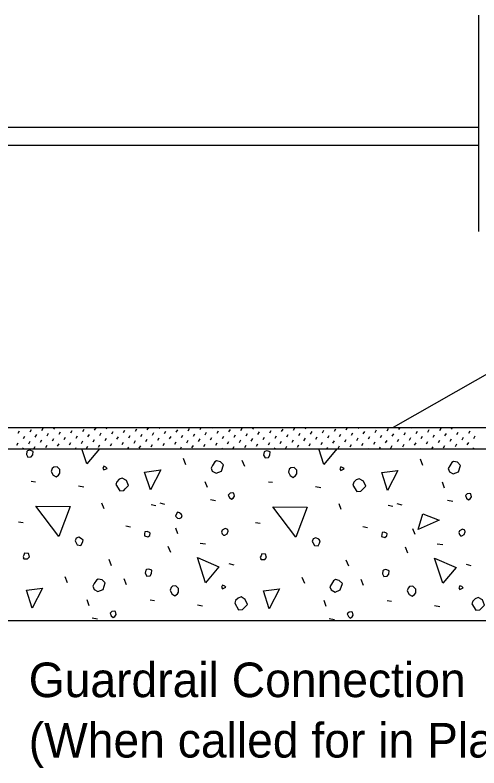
# Model space of a CAD drawing. Extents: x 0 to 41.1, y 0 to 25.9.
# Drawn here: x 34.613 to 37.318, y 9.7 to 14.089 of the extents above; entities that cross this region are included whole.
import ezdxf

# ---------------------------------------------------------------- set-up
doc = ezdxf.new("R2010")
doc.units = 0
for name, color, linetype in [('Dimension', 7, 'Continuous'), ('Miscellaneous', 7, 'Continuous'), ('TrafBarrierConc', 7, 'Continuous')]:
    doc.layers.add(name, color=color, linetype=linetype)

msp = doc.modelspace()

# ---------------------------------------------------------------- linework, layer by layer
at = {"layer": 'Miscellaneous'}
for p, q in [((37.3177, 12.8265), (37.3177, 14.0888)), ((34.77, 11.6673), (34.7781, 11.6813)), ((34.8391, 11.6754), (34.8446, 11.6848)), ((34.9083, 11.6835), (34.909, 11.6848)), ((35.008, 11.6611), (35.0161, 11.6751)), ((35.0772, 11.6692), (35.0853, 11.6832)), ((35.1463, 11.6773), (35.1507, 11.6848)), ((35.3152, 11.663), (35.3233, 11.677)), ((35.3844, 11.6711), (35.3923, 11.6848)), ((35.4535, 11.6792), (35.4568, 11.6848)), ((35.6224, 11.6649), (35.6305, 11.6789)), ((35.6915, 11.673), (35.6984, 11.6848)), ((35.7607, 11.6811), (35.7629, 11.6848)), ((35.9296, 11.6667), (35.9377, 11.6807)), ((35.9987, 11.6748), (36.0045, 11.6848)), ((36.0679, 11.6829), (36.069, 11.6848)), ((36.2368, 11.6686), (36.2449, 11.6826)), ((36.3059, 11.6767), (36.3106, 11.6848)), ((36.4748, 11.6624), (36.4829, 11.6764)), ((36.5439, 11.6705), (36.552, 11.6845)), ((36.6131, 11.6786), (36.6167, 11.6848)), ((36.782, 11.6643), (36.7901, 11.6783)), ((36.8511, 11.6724), (36.8583, 11.6848)), ((36.9203, 11.6805), (36.9228, 11.6848)), ((37.0891, 11.6661), (37.0972, 11.6801)), ((37.1583, 11.6742), (37.1644, 11.6848)), ((37.2275, 11.6823), (37.2289, 11.6848)), ((34.6317, 11.6511), (34.6398, 11.6651)), ((34.6622, 11.6206), (34.6703, 11.6346)), ((34.7008, 11.6592), (34.7089, 11.6732)), ((34.7314, 11.6287), (34.7395, 11.6427)), ((34.8005, 11.6368), (34.8086, 11.6508)), ((34.8697, 11.6449), (34.8778, 11.6589)), ((34.9388, 11.653), (34.9469, 11.667)), ((34.9694, 11.6225), (34.9775, 11.6365)), ((35.0385, 11.6306), (35.0466, 11.6446)), ((35.1077, 11.6387), (35.1158, 11.6527)), ((35.1769, 11.6468), (35.185, 11.6608)), ((35.246, 11.6549), (35.2541, 11.6689)), ((35.2766, 11.6243), (35.2847, 11.6383)), ((35.3457, 11.6324), (35.3538, 11.6464)), ((35.4149, 11.6405), (35.423, 11.6545)), ((35.4841, 11.6487), (35.4922, 11.6626)), ((35.5146, 11.6181), (35.5227, 11.6321)), ((35.5532, 11.6568), (35.5613, 11.6707)), ((35.5837, 11.6262), (35.5918, 11.6402)), ((35.6529, 11.6343), (35.661, 11.6483)), ((35.7221, 11.6424), (35.7302, 11.6564)), ((35.7912, 11.6505), (35.7993, 11.6645)), ((35.8218, 11.62), (35.8299, 11.634)), ((35.8604, 11.6586), (35.8685, 11.6726)), ((35.8909, 11.6281), (35.899, 11.6421)), ((35.9601, 11.6362), (35.9682, 11.6502)), ((36.0293, 11.6443), (36.0374, 11.6583)), ((36.0984, 11.6524), (36.1065, 11.6664)), ((36.129, 11.6219), (36.1371, 11.6359)), ((36.1676, 11.6605), (36.1757, 11.6745)), ((36.1981, 11.63), (36.2062, 11.644)), ((36.2673, 11.6381), (36.2754, 11.6521)), ((36.3364, 11.6462), (36.3445, 11.6602)), ((36.4056, 11.6543), (36.4137, 11.6683)), ((36.4361, 11.6238), (36.4442, 11.6378)), ((36.5053, 11.6319), (36.5134, 11.6459)), ((36.5745, 11.64), (36.5826, 11.654)), ((36.6436, 11.6481), (36.6517, 11.6621)), ((36.6742, 11.6175), (36.6823, 11.6315)), ((36.7128, 11.6562), (36.7209, 11.6702)), ((36.7433, 11.6256), (36.7514, 11.6396)), ((36.8125, 11.6337), (36.8206, 11.6477)), ((36.8817, 11.6418), (36.8898, 11.6558)), ((36.9508, 11.6499), (36.9589, 11.6639)), ((36.9814, 11.6194), (36.9895, 11.6334)), ((37.02, 11.658), (37.0281, 11.672)), ((37.0505, 11.6275), (37.0586, 11.6415)), ((37.1197, 11.6356), (37.1278, 11.6496)), ((37.1888, 11.6437), (37.1969, 11.6577)), ((37.258, 11.6518), (37.2661, 11.6658)), ((37.2885, 11.6213), (37.2966, 11.6353)), ((34.6236, 11.582), (34.6317, 11.596)), ((34.6927, 11.5901), (34.7008, 11.6041)), ((34.7619, 11.5982), (34.77, 11.6122)), ((34.831, 11.6063), (34.8391, 11.6203)), ((34.8616, 11.5757), (34.8697, 11.5897)), ((34.9002, 11.6144), (34.9083, 11.6284)), ((34.9307, 11.5838), (34.9388, 11.5978)), ((34.9999, 11.5919), (35.008, 11.6059)), ((35.0691, 11.6), (35.0772, 11.614)), ((35.1382, 11.6081), (35.1463, 11.6221)), ((35.1688, 11.5776), (35.1769, 11.5916)), ((35.2074, 11.6162), (35.2155, 11.6302)), ((35.2379, 11.5857), (35.246, 11.5997)), ((35.3071, 11.5938), (35.3152, 11.6078)), ((35.3763, 11.6019), (35.3844, 11.6159)), ((35.4454, 11.61), (35.4535, 11.624)), ((35.4759, 11.5795), (35.4841, 11.5935)), ((35.5451, 11.5876), (35.5532, 11.6016)), ((35.6143, 11.5957), (35.6224, 11.6097)), ((35.6834, 11.6038), (35.6915, 11.6178)), ((35.714, 11.5733), (35.7221, 11.5873)), ((35.7526, 11.6119), (35.7607, 11.6259)), ((35.7831, 11.5814), (35.7912, 11.5954)), ((35.8523, 11.5895), (35.8604, 11.6035)), ((35.9215, 11.5976), (35.9296, 11.6116)), ((35.9906, 11.6057), (35.9987, 11.6197)), ((36.0212, 11.5751), (36.0293, 11.5891)), ((36.0598, 11.6138), (36.0679, 11.6278)), ((36.0903, 11.5832), (36.0984, 11.5972)), ((36.1595, 11.5913), (36.1676, 11.6053)), ((36.2286, 11.5994), (36.2368, 11.6134)), ((36.2978, 11.6076), (36.3059, 11.6215)), ((36.3283, 11.577), (36.3364, 11.591)), ((36.367, 11.6157), (36.3751, 11.6296)), ((36.3975, 11.5851), (36.4056, 11.5991)), ((36.4667, 11.5932), (36.4748, 11.6072)), ((36.5358, 11.6013), (36.5439, 11.6153)), ((36.605, 11.6094), (36.6131, 11.6234)), ((36.6355, 11.5789), (36.6436, 11.5929)), ((36.7047, 11.587), (36.7128, 11.601)), ((36.7739, 11.5951), (36.782, 11.6091)), ((36.843, 11.6032), (36.8511, 11.6172)), ((36.9122, 11.6113), (36.9203, 11.6253)), ((36.9427, 11.5808), (36.9508, 11.5948)), ((37.0119, 11.5889), (37.02, 11.6029)), ((37.081, 11.597), (37.0891, 11.611)), ((37.1502, 11.6051), (37.1583, 11.6191)), ((37.1807, 11.5746), (37.1888, 11.5885)), ((37.2194, 11.6132), (37.2275, 11.6272)), ((37.2499, 11.5827), (37.258, 11.5966)), ((34.6589, 11.5598), (34.6622, 11.5654)), ((34.7234, 11.5598), (34.7314, 11.5735)), ((34.7924, 11.5676), (34.8005, 11.5816)), ((34.965, 11.5598), (34.9694, 11.5673)), ((35.0304, 11.5614), (35.0385, 11.5754)), ((35.0996, 11.5695), (35.1077, 11.5835)), ((35.2067, 11.5598), (35.2074, 11.5611)), ((35.2711, 11.5598), (35.2766, 11.5692)), ((35.3376, 11.5633), (35.3457, 11.5773)), ((35.4068, 11.5714), (35.4149, 11.5854)), ((35.5128, 11.5598), (35.5146, 11.563)), ((35.5772, 11.5598), (35.5837, 11.5711)), ((35.6448, 11.5652), (35.6529, 11.5792)), ((35.8189, 11.5598), (35.8218, 11.5648)), ((35.8833, 11.5598), (35.8909, 11.5729)), ((35.952, 11.567), (35.9601, 11.581)), ((36.125, 11.5598), (36.129, 11.5667)), ((36.19, 11.5608), (36.1981, 11.5748)), ((36.2592, 11.5689), (36.2673, 11.5829)), ((36.3666, 11.5598), (36.367, 11.5605)), ((36.4311, 11.5598), (36.4361, 11.5686)), ((36.4972, 11.5627), (36.5053, 11.5767)), ((36.5664, 11.5708), (36.5745, 11.5848)), ((36.6727, 11.5598), (36.6742, 11.5624)), ((36.7371, 11.5598), (36.7433, 11.5705)), ((36.8044, 11.5646), (36.8125, 11.5786)), ((36.8736, 11.5727), (36.8817, 11.5867)), ((36.9788, 11.5598), (36.9814, 11.5642)), ((37.0432, 11.5598), (37.0505, 11.5723)), ((37.1116, 11.5665), (37.1197, 11.5804)), ((37.2849, 11.5598), (37.2885, 11.5661)), ((35.6092, 11.4675), (35.595, 11.5028)), ((36.9915, 11.4639), (36.9774, 11.4993)), ((35.9521, 11.4569), (35.938, 11.4922)), ((34.7076, 11.372), (34.7323, 11.3685)), ((35.7347, 11.3349), (35.7223, 11.3685)), ((36.09, 11.3685), (36.1147, 11.3649)), ((34.9834, 11.3437), (35.0134, 11.3384)), ((36.3658, 11.3402), (36.3958, 11.3349)), ((37.1171, 11.3313), (37.1047, 11.3649)), ((35.1319, 11.2094), (35.1195, 11.243)), ((35.4059, 11.2359), (35.4341, 11.2288)), ((35.4571, 11.2447), (35.4854, 11.2377)), ((35.7523, 11.2642), (35.7824, 11.2589)), ((36.5142, 11.2058), (36.5019, 11.2394)), ((36.8395, 11.2412), (36.8678, 11.2341)), ((37.1347, 11.2606), (37.1648, 11.2553)), ((36.7883, 11.2324), (36.8165, 11.2253)), ((34.6333, 11.1351), (34.6599, 11.1298)), ((35.2591, 11.1104), (35.2857, 11.1051)), ((36.0157, 11.1316), (36.0423, 11.1263)), ((36.6415, 11.1068), (36.668, 11.1015)), ((35.5632, 11.0644), (35.5508, 11.098)), ((36.9456, 11.0609), (36.9332, 11.0945)), ((35.5208, 10.9548), (35.5066, 10.9902)), ((35.6922, 11.0096), (35.7241, 11.0061)), ((36.9032, 10.9513), (36.889, 10.9866)), ((37.0746, 11.0061), (37.1065, 11.0025)), ((35.176, 10.8788), (35.1619, 10.9142)), ((35.8602, 10.8912), (35.8885, 10.8841)), ((36.5584, 10.8753), (36.5443, 10.9106)), ((37.2426, 10.8876), (37.2709, 10.8806)), ((34.9197, 10.778), (34.9056, 10.8134)), ((35.2627, 10.7674), (35.2485, 10.8028)), ((36.3021, 10.7745), (36.288, 10.8099)), ((36.6451, 10.7639), (36.6309, 10.7992)), ((35.0452, 10.6455), (35.0329, 10.679)), ((35.4006, 10.679), (35.4253, 10.6755)), ((36.4276, 10.6419), (36.4153, 10.6755)), ((36.7829, 10.6755), (36.8077, 10.672)), ((35.6763, 10.6508), (35.7064, 10.6455)), ((37.0587, 10.6472), (37.0888, 10.6419)), ((35.0629, 10.5747), (35.093, 10.5694)), ((36.4453, 10.5712), (36.4754, 10.5659))]:
    msp.add_line(p, q, dxfattribs=at)
for points in [[(34.6793, 11.5276), (34.6881, 11.5117), (34.7076, 11.5134), (34.7164, 11.5258), (34.7182, 11.5452), (34.7058, 11.5505), (34.697, 11.5523), (34.6864, 11.5488), (34.6828, 11.5452), (34.6793, 11.5276)], [(35.0311, 11.4728), (35.0028, 11.5598)], [(35.1047, 11.5598), (35.0311, 11.4728)], [(36.0617, 11.524), (36.0705, 11.5081), (36.09, 11.5099), (36.0988, 11.5223), (36.1006, 11.5417), (36.0882, 11.547), (36.0794, 11.5488), (36.0688, 11.5452), (36.0652, 11.5417), (36.0617, 11.524)], [(36.4135, 11.4692), (36.384, 11.5598)], [(36.4901, 11.5598), (36.4135, 11.4692)], [(35.1301, 11.4374), (35.1495, 11.4463), (35.1425, 11.4533), (35.1301, 11.4586), (35.1248, 11.4463), (35.1301, 11.4374)], [(35.7629, 11.4303), (35.7859, 11.418), (35.816, 11.4303), (35.8284, 11.4675), (35.8107, 11.4851), (35.7877, 11.4904), (35.7771, 11.4834), (35.7647, 11.4639), (35.7559, 11.448), (35.7629, 11.4303)], [(37.1453, 11.4268), (37.1683, 11.4144), (37.1984, 11.4268), (37.2107, 11.4639), (37.1931, 11.4816), (37.1701, 11.4869), (37.1595, 11.4798), (37.1471, 11.4604), (37.1383, 11.4445), (37.1453, 11.4268)], [(34.8243, 11.4286), (34.8349, 11.4074), (34.8525, 11.3968), (34.8667, 11.4074), (34.8738, 11.418), (34.8738, 11.4392), (34.8579, 11.4551), (34.8384, 11.4533), (34.8296, 11.4445), (34.8243, 11.4286)], [(35.4023, 11.3207), (35.3687, 11.425), (35.4624, 11.4374), (35.4023, 11.3207)], [(36.2067, 11.425), (36.2173, 11.4038), (36.2349, 11.3932), (36.2491, 11.4038), (36.2562, 11.4144), (36.2562, 11.4356), (36.2402, 11.4516), (36.2208, 11.4498), (36.212, 11.4409), (36.2067, 11.425)], [(36.5125, 11.4339), (36.5319, 11.4427), (36.5249, 11.4498), (36.5125, 11.4551), (36.5072, 11.4427), (36.5125, 11.4339)], [(36.7847, 11.3172), (36.7511, 11.4215), (36.8448, 11.4339), (36.7847, 11.3172)], [(35.2008, 11.3526), (35.2238, 11.3154), (35.2468, 11.3172), (35.2556, 11.326), (35.275, 11.3455), (35.2627, 11.3755), (35.2379, 11.3897), (35.2202, 11.3826), (35.2061, 11.3685), (35.2008, 11.3526)], [(36.5832, 11.349), (36.6062, 11.3119), (36.6292, 11.3137), (36.638, 11.3225), (36.6574, 11.342), (36.6451, 11.372), (36.6203, 11.3861), (36.6026, 11.3791), (36.5885, 11.3649), (36.5832, 11.349)], [(35.8637, 11.2765), (35.8743, 11.2659), (35.8849, 11.273), (35.892, 11.2836), (35.8885, 11.3013), (35.8796, 11.3031), (35.8672, 11.3013), (35.8566, 11.2907), (35.8637, 11.2765)], [(37.2461, 11.273), (37.2567, 11.2624), (37.2673, 11.2695), (37.2744, 11.2801), (37.2709, 11.2978), (37.262, 11.2995), (37.2496, 11.2978), (37.239, 11.2872), (37.2461, 11.273)], [(34.8685, 11.0485), (34.7341, 11.2253), (34.9339, 11.2235), (34.8685, 11.0485)], [(36.2509, 11.045), (36.1165, 11.2217), (36.3163, 11.22), (36.2509, 11.045)], [(35.5597, 11.1563), (35.572, 11.1546), (35.5844, 11.1599), (35.5879, 11.1705), (35.5826, 11.1793), (35.572, 11.1864), (35.5597, 11.1917), (35.5526, 11.1776), (35.549, 11.1669), (35.5597, 11.1563)], [(36.9633, 11.0892), (36.9915, 11.1811), (37.0852, 11.144), (36.9633, 11.0892)], [(35.367, 11.052), (35.3864, 11.0467), (35.3988, 11.0556), (35.4006, 11.0679), (35.397, 11.0715), (35.3829, 11.0786), (35.3705, 11.0768), (35.3687, 11.0644), (35.367, 11.052)], [(35.8284, 11.0573), (35.8354, 11.0573), (35.8496, 11.0644), (35.8549, 11.0803), (35.8531, 11.0892), (35.839, 11.0962), (35.8213, 11.0856), (35.8177, 11.075), (35.8213, 11.0644), (35.8284, 11.0573)], [(36.7494, 11.0485), (36.7688, 11.0432), (36.7812, 11.052), (36.7829, 11.0644), (36.7794, 11.0679), (36.7653, 11.075), (36.7529, 11.0733), (36.7511, 11.0609), (36.7494, 11.0485)], [(37.2107, 11.0538), (37.2178, 11.0538), (37.232, 11.0609), (37.2373, 11.0768), (37.2355, 11.0856), (37.2214, 11.0927), (37.2037, 11.0821), (37.2001, 11.0715), (37.2037, 11.0609), (37.2107, 11.0538)], [(34.9675, 11.0167), (34.9763, 11.0008), (34.9975, 10.9972), (35.0063, 11.0131), (35.0099, 11.0273), (35.001, 11.0361), (34.9851, 11.045), (34.9692, 11.0397), (34.9639, 11.0238), (34.9675, 11.0167)], [(36.3498, 11.0131), (36.3587, 10.9972), (36.3799, 10.9937), (36.3887, 11.0096), (36.3923, 11.0238), (36.3834, 11.0326), (36.3675, 11.0414), (36.3516, 11.0361), (36.3463, 11.0202), (36.3498, 11.0131)], [(34.6652, 10.9195), (34.6864, 10.9195), (34.697, 10.9301), (34.6917, 10.9495), (34.6687, 10.9513), (34.6652, 10.9407), (34.6599, 10.9318), (34.6652, 10.9195), (34.6616, 10.923)], [(36.0476, 10.9159), (36.0688, 10.9159), (36.0794, 10.9265), (36.0741, 10.946), (36.0511, 10.9477), (36.0476, 10.9371), (36.0423, 10.9283), (36.0476, 10.9159), (36.044, 10.9195)], [(35.7241, 10.7798), (35.6763, 10.9265), (35.8018, 10.8717), (35.7241, 10.7798)], [(37.1065, 10.7763), (37.0587, 10.923), (37.1842, 10.8682), (37.1065, 10.7763)], [(35.3723, 10.8346), (35.3811, 10.8187), (35.4006, 10.8205), (35.4094, 10.8328), (35.4112, 10.8523), (35.3988, 10.8576), (35.3899, 10.8594), (35.3793, 10.8558), (35.3758, 10.8523), (35.3723, 10.8346)], [(36.7547, 10.8311), (36.7635, 10.8152), (36.7829, 10.8169), (36.7918, 10.8293), (36.7936, 10.8487), (36.7812, 10.854), (36.7723, 10.8558), (36.7617, 10.8523), (36.7582, 10.8487), (36.7547, 10.8311)], [(35.0735, 10.7409), (35.0965, 10.7285), (35.1266, 10.7409), (35.1389, 10.778), (35.1212, 10.7957), (35.0983, 10.801), (35.0877, 10.7939), (35.0753, 10.7745), (35.0664, 10.7586), (35.0735, 10.7409)], [(36.4559, 10.7374), (36.4789, 10.725), (36.5089, 10.7374), (36.5213, 10.7745), (36.5036, 10.7922), (36.4807, 10.7975), (36.4701, 10.7904), (36.4577, 10.771), (36.4488, 10.7551), (36.4559, 10.7374)], [(35.5172, 10.7356), (35.5278, 10.7144), (35.5455, 10.7038), (35.5597, 10.7144), (35.5667, 10.725), (35.5667, 10.7462), (35.5508, 10.7621), (35.5314, 10.7604), (35.5225, 10.7515), (35.5172, 10.7356)], [(35.8231, 10.7444), (35.8425, 10.7533), (35.8354, 10.7604), (35.8231, 10.7657), (35.8177, 10.7533), (35.8231, 10.7444)], [(36.8996, 10.7321), (36.9102, 10.7109), (36.9279, 10.7003), (36.942, 10.7109), (36.9491, 10.7215), (36.9491, 10.7427), (36.9332, 10.7586), (36.9138, 10.7568), (36.9049, 10.748), (36.8996, 10.7321)], [(37.2054, 10.7409), (37.2249, 10.7498), (37.2178, 10.7568), (37.2054, 10.7621), (37.2001, 10.7498), (37.2054, 10.7409)], [(34.7129, 10.6313), (34.6793, 10.7356), (34.773, 10.748), (34.7129, 10.6313)], [(36.0953, 10.6278), (36.0617, 10.7321), (36.1554, 10.7444), (36.0953, 10.6278)], [(35.8938, 10.6596), (35.9167, 10.6225), (35.9397, 10.6242), (35.9486, 10.6331), (35.968, 10.6525), (35.9556, 10.6826), (35.9309, 10.6967), (35.9132, 10.6896), (35.8991, 10.6755), (35.8938, 10.6596)], [(37.2762, 10.6561), (37.2991, 10.6189), (37.3221, 10.6207), (37.331, 10.6295), (37.3504, 10.649), (37.338, 10.679), (37.3133, 10.6932), (37.2956, 10.6861), (37.2815, 10.672), (37.2762, 10.6561)], [(35.1743, 10.5871), (35.1849, 10.5765), (35.1955, 10.5836), (35.2026, 10.5942), (35.199, 10.6119), (35.1902, 10.6136), (35.1778, 10.6119), (35.1672, 10.6013), (35.1743, 10.5871)], [(36.5567, 10.5836), (36.5673, 10.573), (36.5779, 10.58), (36.585, 10.5907), (36.5814, 10.6083), (36.5726, 10.6101), (36.5602, 10.6083), (36.5496, 10.5977), (36.5567, 10.5836)]]:
    msp.add_lwpolyline(points, dxfattribs=at)
at = {"layer": 'TrafBarrierConc'}
for p, q in [((23.987, 13.4349), (37.3177, 13.4349)), ((39.8176, 13.3931), (36.8179, 11.6848)), ((23.987, 13.3307), (37.3177, 13.3307)), ((23.987, 11.6848), (39.8181, 11.6848)), ((23.987, 11.5598), (39.8181, 11.5598)), ((23.987, 10.5598), (39.8181, 10.5598))]:
    msp.add_line(p, q, dxfattribs=at)

# ---------------------------------------------------------------- texts
at = {"layer": 'Dimension'}
for s, p in [('Guardrail Connection', (34.6929, 10.1125)), ('(When called for in Plans)', (34.6929, 9.7605))]:
    msp.add_text(s, height=0.2016, dxfattribs=at).set_placement(p)

doc.saveas('drawing.dxf')
